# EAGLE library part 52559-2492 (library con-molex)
FFC/FPC-to-Board 0.50mm (.020") SMT, Vertical, ZIF Receptacle Source: http://www.molex.com/product/ffc/52559.html
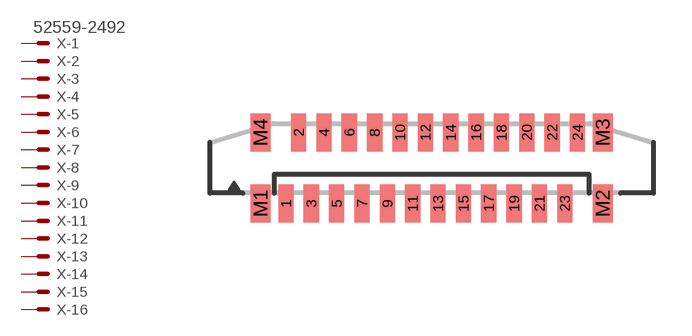
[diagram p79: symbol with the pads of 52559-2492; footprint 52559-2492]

Designator prefix X; gates -1=MV -2=M -3=M -4=M -5=M -6=M -7=M -8=M -9=M -10=M -11=M -12=M -13=M -14=M -15=M -16=M -17=M -18=M -19=M -20=M -21=M -22=M -23=M -24=M

## 52559-2492 (MPN: 52559-2492; OC_FARNELL: unknown; OC_NEWARK: 25M4409)  [52559-2492]
1  -1:S  pas
2  -2:S  pas
3  -3:S  pas
4  -4:S  pas
5  -5:S  pas
6  -6:S  pas
7  -7:S  pas
8  -8:S  pas
9  -9:S  pas
10  -10:S  pas
11  -11:S  pas
12  -12:S  pas
13  -13:S  pas
14  -14:S  pas
15  -15:S  pas
16  -16:S  pas
17  -17:S  pas
18  -18:S  pas
19  -19:S  pas
20  -20:S  pas
21  -21:S  pas
22  -22:S  pas
23  -23:S  pas
24  -24:S  pas

## Footprint 52559-2492 (pad centres in mm)
FFC/FPC-to-Board 0.50mm (.020") SMT, Vertical, ZIF Receptacle Source: http://www.molex.com/product/ffc/52559.html
smd 0.6 x 1.5: 1 -5.75,-1.4; 2 -5.25,1.4; 3 -4.75,-1.4; 4 -4.25,1.4; 5 -3.75,-1.4; 6 -3.25,1.4; 7 -2.75,-1.4; 8 -2.25,1.4; 9 -1.75,-1.4; 10 -1.25,1.4; 11 -0.75,-1.4; 12 -0.25,1.4; 13 0.25,-1.4; 14 0.75,1.4; 15 1.25,-1.4; 16 1.75,1.4; 17 2.25,-1.4; 18 2.75,1.4; 19 3.25,-1.4; 20 3.75,1.4; 21 4.25,-1.4; 22 4.75,1.4; 23 5.25,-1.4; 24 5.75,1.4
smd 0.8 x 1.5: M1 -6.75,-1.4; M2 6.75,-1.4; M3 6.75,1.4; M4 -6.75,1.4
